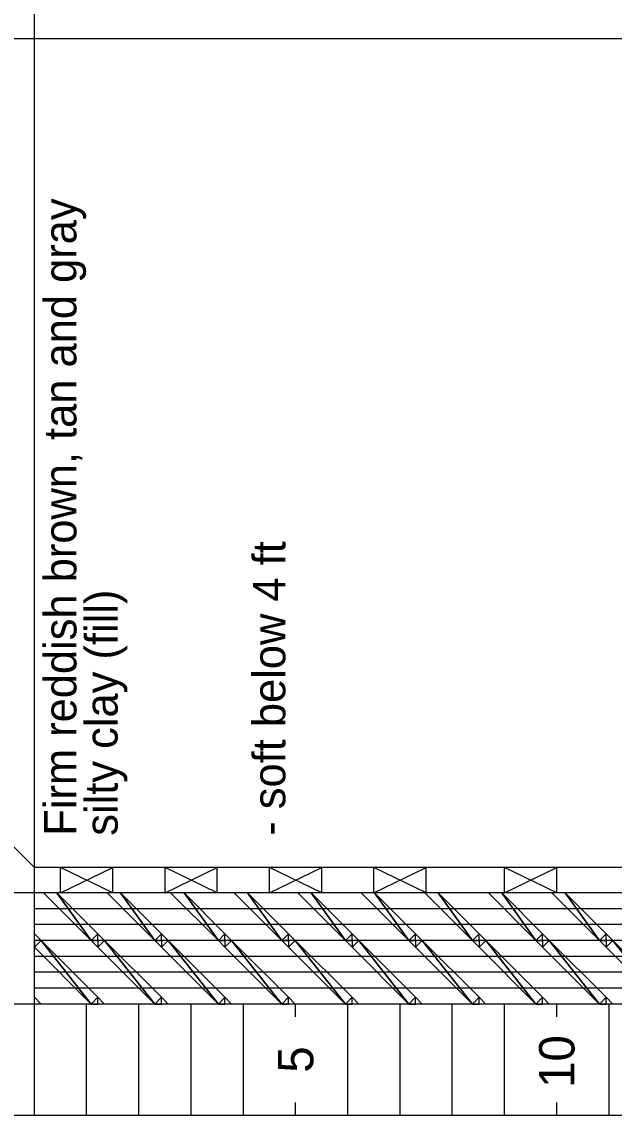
# Model space of a CAD drawing. Extents: x 1313964 to 1316843, y 2087046 to 2096619.
# Drawn here: x 1313989.13 to 1314000.47, y 2089818.7 to 2089839.64 of the extents above; entities that cross this region are included whole.
import ezdxf

# ---------------------------------------------------------------- set-up
doc = ezdxf.new("R2010")
doc.units = 0
doc.layers.add('B-Sub-Contour', color=7, linetype='Continuous')

msp = doc.modelspace()

# ---------------------------------------------------------------- linework, layer by layer
at = {"layer": 'B-Sub-Contour'}
for points in [[(1314036.804, 2089818.705), (1314036.804, 2089861.576), (1313975.385, 2089861.576), (1313975.385, 2089818.705), (1314036.804, 2089818.705)], [(1313989.372, 2089818.705), (1313989.372, 2089861.576)], [(1314034.372, 2089839.319), (1313982.683, 2089839.319)], [(1313989.372, 2089823.448), (1313988.824, 2089823.995)], [(1314034.372, 2089823.448), (1313989.372, 2089823.448)], [(1313989.872, 2089822.961), (1313990.872, 2089823.448)], [(1313990.872, 2089822.961), (1313989.872, 2089823.448)], [(1313989.872, 2089822.961), (1313989.872, 2089823.448)], [(1313990.872, 2089822.961), (1313990.872, 2089823.448)], [(1313991.872, 2089822.961), (1313992.872, 2089823.448)], [(1313992.872, 2089822.961), (1313991.872, 2089823.448)], [(1313991.872, 2089822.961), (1313991.872, 2089823.448)], [(1313992.872, 2089822.961), (1313992.872, 2089823.448)], [(1313993.872, 2089822.961), (1313994.872, 2089823.448)], [(1313994.872, 2089822.961), (1313993.872, 2089823.448)], [(1313993.872, 2089822.961), (1313993.872, 2089823.448)], [(1313994.872, 2089822.961), (1313994.872, 2089823.448)], [(1313995.872, 2089822.961), (1313996.872, 2089823.448)], [(1313996.872, 2089822.961), (1313995.872, 2089823.448)], [(1313995.872, 2089822.961), (1313995.872, 2089823.448)], [(1313996.872, 2089822.961), (1313996.872, 2089823.448)], [(1313998.372, 2089822.961), (1313999.372, 2089823.448)], [(1313999.372, 2089822.961), (1313998.372, 2089823.448)], [(1313998.372, 2089822.961), (1313998.372, 2089823.448)], [(1313999.372, 2089822.961), (1313999.372, 2089823.448)], [(1314034.372, 2089822.961), (1313982.683, 2089822.961)], [(1314002.372, 2089822.657), (1313989.372, 2089822.657)], [(1314002.372, 2089822.353), (1313989.372, 2089822.353)], [(1314002.372, 2089822.049), (1313989.372, 2089822.049)], [(1314002.372, 2089821.745), (1313989.372, 2089821.745)], [(1314002.372, 2089821.441), (1313989.372, 2089821.441)], [(1314002.372, 2089821.137), (1313989.372, 2089821.137)], [(1314034.372, 2089820.833), (1313982.683, 2089820.833)], [(1313989.372, 2089820.59), (1313989.372, 2089820.833)], [(1313989.372, 2089820.59), (1313989.372, 2089820.833)], [(1313990.372, 2089818.705), (1313990.372, 2089820.833)], [(1313991.372, 2089818.705), (1313991.372, 2089820.833)], [(1313991.372, 2089818.705), (1313991.372, 2089820.833)], [(1313992.372, 2089818.705), (1313992.372, 2089820.833)], [(1313993.372, 2089818.705), (1313993.372, 2089820.833)], [(1313993.372, 2089818.705), (1313993.372, 2089820.833)], [(1313994.372, 2089820.59), (1313994.372, 2089820.833)], [(1313995.372, 2089818.705), (1313995.372, 2089820.833)], [(1313995.372, 2089818.705), (1313995.372, 2089820.833)], [(1313996.372, 2089818.705), (1313996.372, 2089820.833)], [(1313997.372, 2089818.705), (1313997.372, 2089820.833)], [(1313997.372, 2089818.705), (1313997.372, 2089820.833)], [(1313998.372, 2089818.705), (1313998.372, 2089820.833)], [(1313999.372, 2089820.59), (1313999.372, 2089820.833)], [(1313999.372, 2089820.59), (1313999.372, 2089820.833)], [(1314000.372, 2089818.705), (1314000.372, 2089820.833)], [(1313989.372, 2089818.705), (1313989.372, 2089818.948)], [(1313989.372, 2089818.705), (1313989.372, 2089818.948)], [(1313994.372, 2089818.705), (1313994.372, 2089818.948)], [(1313999.372, 2089818.705), (1313999.372, 2089818.948)], [(1313999.372, 2089818.705), (1313999.372, 2089818.948)]]:
    msp.add_lwpolyline(points, dxfattribs=at)
for points in [[(1313990.46, 2089822.049), (1313989.803, 2089822.961), (1313989.548, 2089822.961), (1313990.46, 2089822.049)], [(1313990.46, 2089822.049), (1313990.588, 2089822.177), (1313989.803, 2089822.961), (1313990.46, 2089822.049)], [(1313991.676, 2089822.049), (1313991.02, 2089822.961), (1313990.764, 2089822.961), (1313991.676, 2089822.049)], [(1313991.676, 2089822.049), (1313991.804, 2089822.177), (1313991.02, 2089822.961), (1313991.676, 2089822.049)], [(1313992.893, 2089822.049), (1313992.236, 2089822.961), (1313991.98, 2089822.961), (1313992.893, 2089822.049)], [(1313992.893, 2089822.049), (1313993.02, 2089822.177), (1313992.236, 2089822.961), (1313992.893, 2089822.049)], [(1313994.109, 2089822.049), (1313993.452, 2089822.961), (1313993.197, 2089822.961), (1313994.109, 2089822.049)], [(1313994.109, 2089822.049), (1313994.237, 2089822.177), (1313993.452, 2089822.961), (1313994.109, 2089822.049)], [(1313995.325, 2089822.049), (1313994.668, 2089822.961), (1313994.413, 2089822.961), (1313995.325, 2089822.049)], [(1313995.325, 2089822.049), (1313995.453, 2089822.177), (1313994.668, 2089822.961), (1313995.325, 2089822.049)], [(1313996.541, 2089822.049), (1313995.885, 2089822.961), (1313995.629, 2089822.961), (1313996.541, 2089822.049)], [(1313996.541, 2089822.049), (1313996.669, 2089822.177), (1313995.885, 2089822.961), (1313996.541, 2089822.049)], [(1313997.757, 2089822.049), (1313997.101, 2089822.961), (1313996.845, 2089822.961), (1313997.757, 2089822.049)], [(1313997.757, 2089822.049), (1313997.885, 2089822.177), (1313997.101, 2089822.961), (1313997.757, 2089822.049)], [(1313998.974, 2089822.049), (1313998.317, 2089822.961), (1313998.062, 2089822.961), (1313998.974, 2089822.049)], [(1313998.974, 2089822.049), (1313999.101, 2089822.177), (1313998.317, 2089822.961), (1313998.974, 2089822.049)], [(1314000.19, 2089822.049), (1313999.533, 2089822.961), (1313999.278, 2089822.961), (1314000.19, 2089822.049)], [(1314000.19, 2089822.049), (1314000.318, 2089822.177), (1313999.533, 2089822.961), (1314000.19, 2089822.049)], [(1313989.499, 2089822.049), (1313989.372, 2089822.049), (1313989.372, 2089822.177), (1313989.499, 2089822.049)], [(1313989.499, 2089822.049), (1313989.372, 2089822.049), (1313989.372, 2089821.922), (1313989.499, 2089822.049)], [(1313990.46, 2089820.833), (1313989.499, 2089822.049), (1313989.372, 2089821.922), (1313990.46, 2089820.833)], [(1313990.46, 2089820.833), (1313990.588, 2089820.961), (1313989.499, 2089822.049), (1313990.46, 2089820.833)], [(1313990.46, 2089822.049), (1313990.588, 2089822.049), (1313990.588, 2089822.177), (1313990.46, 2089822.049)], [(1313990.588, 2089822.049), (1313990.588, 2089821.922), (1313990.46, 2089822.049), (1313990.588, 2089822.049)], [(1313990.716, 2089822.049), (1313990.588, 2089822.049), (1313990.588, 2089822.177), (1313990.716, 2089822.049)], [(1313990.716, 2089822.049), (1313990.588, 2089822.049), (1313990.588, 2089821.922), (1313990.716, 2089822.049)], [(1313991.676, 2089820.833), (1313990.716, 2089822.049), (1313990.588, 2089821.922), (1313991.676, 2089820.833)], [(1313991.676, 2089820.833), (1313991.804, 2089820.961), (1313990.716, 2089822.049), (1313991.676, 2089820.833)], [(1313991.676, 2089822.049), (1313991.804, 2089822.049), (1313991.804, 2089822.177), (1313991.676, 2089822.049)], [(1313991.804, 2089822.049), (1313991.804, 2089821.922), (1313991.676, 2089822.049), (1313991.804, 2089822.049)], [(1313991.932, 2089822.049), (1313991.804, 2089822.049), (1313991.804, 2089822.177), (1313991.932, 2089822.049)], [(1313991.932, 2089822.049), (1313991.804, 2089822.049), (1313991.804, 2089821.922), (1313991.932, 2089822.049)], [(1313992.893, 2089820.833), (1313991.932, 2089822.049), (1313991.804, 2089821.922), (1313992.893, 2089820.833)], [(1313992.893, 2089820.833), (1313993.02, 2089820.961), (1313991.932, 2089822.049), (1313992.893, 2089820.833)], [(1313992.893, 2089822.049), (1313993.02, 2089822.049), (1313993.02, 2089822.177), (1313992.893, 2089822.049)], [(1313993.02, 2089822.049), (1313993.02, 2089821.922), (1313992.893, 2089822.049), (1313993.02, 2089822.049)], [(1313993.148, 2089822.049), (1313993.02, 2089822.049), (1313993.02, 2089822.177), (1313993.148, 2089822.049)], [(1313993.148, 2089822.049), (1313993.02, 2089822.049), (1313993.02, 2089821.922), (1313993.148, 2089822.049)], [(1313994.109, 2089820.833), (1313993.148, 2089822.049), (1313993.02, 2089821.922), (1313994.109, 2089820.833)], [(1313994.109, 2089820.833), (1313994.237, 2089820.961), (1313993.148, 2089822.049), (1313994.109, 2089820.833)], [(1313994.109, 2089822.049), (1313994.237, 2089822.049), (1313994.237, 2089822.177), (1313994.109, 2089822.049)], [(1313994.237, 2089822.049), (1313994.237, 2089821.922), (1313994.109, 2089822.049), (1313994.237, 2089822.049)], [(1313994.364, 2089822.049), (1313994.237, 2089822.049), (1313994.237, 2089822.177), (1313994.364, 2089822.049)], [(1313994.364, 2089822.049), (1313994.237, 2089822.049), (1313994.237, 2089821.922), (1313994.364, 2089822.049)], [(1313995.325, 2089820.833), (1313994.364, 2089822.049), (1313994.237, 2089821.922), (1313995.325, 2089820.833)], [(1313995.325, 2089820.833), (1313995.453, 2089820.961), (1313994.364, 2089822.049), (1313995.325, 2089820.833)], [(1313995.325, 2089822.049), (1313995.453, 2089822.049), (1313995.453, 2089822.177), (1313995.325, 2089822.049)], [(1313995.453, 2089822.049), (1313995.453, 2089821.922), (1313995.325, 2089822.049), (1313995.453, 2089822.049)], [(1313995.58, 2089822.049), (1313995.453, 2089822.049), (1313995.453, 2089822.177), (1313995.58, 2089822.049)], [(1313995.58, 2089822.049), (1313995.453, 2089822.049), (1313995.453, 2089821.922), (1313995.58, 2089822.049)], [(1313996.541, 2089820.833), (1313995.58, 2089822.049), (1313995.453, 2089821.922), (1313996.541, 2089820.833)], [(1313996.541, 2089820.833), (1313996.669, 2089820.961), (1313995.58, 2089822.049), (1313996.541, 2089820.833)], [(1313996.541, 2089822.049), (1313996.669, 2089822.049), (1313996.669, 2089822.177), (1313996.541, 2089822.049)], [(1313996.669, 2089822.049), (1313996.669, 2089821.922), (1313996.541, 2089822.049), (1313996.669, 2089822.049)], [(1313996.797, 2089822.049), (1313996.669, 2089822.049), (1313996.669, 2089822.177), (1313996.797, 2089822.049)], [(1313996.797, 2089822.049), (1313996.669, 2089822.049), (1313996.669, 2089821.922), (1313996.797, 2089822.049)], [(1313997.757, 2089820.833), (1313996.797, 2089822.049), (1313996.669, 2089821.922), (1313997.757, 2089820.833)], [(1313997.757, 2089820.833), (1313997.885, 2089820.961), (1313996.797, 2089822.049), (1313997.757, 2089820.833)], [(1313997.757, 2089822.049), (1313997.885, 2089822.049), (1313997.885, 2089822.177), (1313997.757, 2089822.049)], [(1313997.885, 2089822.049), (1313997.885, 2089821.922), (1313997.757, 2089822.049), (1313997.885, 2089822.049)], [(1313998.013, 2089822.049), (1313997.885, 2089822.049), (1313997.885, 2089822.177), (1313998.013, 2089822.049)], [(1313998.013, 2089822.049), (1313997.885, 2089822.049), (1313997.885, 2089821.922), (1313998.013, 2089822.049)], [(1313998.974, 2089820.833), (1313998.013, 2089822.049), (1313997.885, 2089821.922), (1313998.974, 2089820.833)], [(1313998.974, 2089820.833), (1313999.101, 2089820.961), (1313998.013, 2089822.049), (1313998.974, 2089820.833)], [(1313998.974, 2089822.049), (1313999.101, 2089822.049), (1313999.101, 2089822.177), (1313998.974, 2089822.049)], [(1313999.101, 2089822.049), (1313999.101, 2089821.922), (1313998.974, 2089822.049), (1313999.101, 2089822.049)], [(1313999.229, 2089822.049), (1313999.101, 2089822.049), (1313999.101, 2089822.177), (1313999.229, 2089822.049)], [(1313999.229, 2089822.049), (1313999.101, 2089822.049), (1313999.101, 2089821.922), (1313999.229, 2089822.049)], [(1314000.19, 2089820.833), (1313999.229, 2089822.049), (1313999.101, 2089821.922), (1314000.19, 2089820.833)], [(1314000.19, 2089820.833), (1314000.318, 2089820.961), (1313999.229, 2089822.049), (1314000.19, 2089820.833)], [(1314000.19, 2089822.049), (1314000.318, 2089822.049), (1314000.318, 2089822.177), (1314000.19, 2089822.049)], [(1314000.318, 2089822.049), (1314000.318, 2089821.922), (1314000.19, 2089822.049), (1314000.318, 2089822.049)], [(1314000.445, 2089822.049), (1314000.318, 2089822.049), (1314000.318, 2089822.177), (1314000.445, 2089822.049)], [(1314000.445, 2089822.049), (1314000.318, 2089822.049), (1314000.318, 2089821.922), (1314000.445, 2089822.049)], [(1314001.406, 2089820.833), (1314000.445, 2089822.049), (1314000.318, 2089821.922), (1314001.406, 2089820.833)], [(1314001.406, 2089820.833), (1314001.534, 2089820.961), (1314000.445, 2089822.049), (1314001.406, 2089820.833)], [(1313989.499, 2089820.833), (1313989.372, 2089820.833), (1313989.372, 2089820.961), (1313989.499, 2089820.833)], [(1313990.46, 2089820.833), (1313990.588, 2089820.833), (1313990.588, 2089820.961), (1313990.46, 2089820.833)], [(1313990.716, 2089820.833), (1313990.588, 2089820.833), (1313990.588, 2089820.961), (1313990.716, 2089820.833)], [(1313991.676, 2089820.833), (1313991.804, 2089820.833), (1313991.804, 2089820.961), (1313991.676, 2089820.833)], [(1313991.932, 2089820.833), (1313991.804, 2089820.833), (1313991.804, 2089820.961), (1313991.932, 2089820.833)], [(1313992.893, 2089820.833), (1313993.02, 2089820.833), (1313993.02, 2089820.961), (1313992.893, 2089820.833)], [(1313993.148, 2089820.833), (1313993.02, 2089820.833), (1313993.02, 2089820.961), (1313993.148, 2089820.833)], [(1313994.109, 2089820.833), (1313994.237, 2089820.833), (1313994.237, 2089820.961), (1313994.109, 2089820.833)], [(1313994.364, 2089820.833), (1313994.237, 2089820.833), (1313994.237, 2089820.961), (1313994.364, 2089820.833)], [(1313995.325, 2089820.833), (1313995.453, 2089820.833), (1313995.453, 2089820.961), (1313995.325, 2089820.833)], [(1313995.58, 2089820.833), (1313995.453, 2089820.833), (1313995.453, 2089820.961), (1313995.58, 2089820.833)], [(1313996.541, 2089820.833), (1313996.669, 2089820.833), (1313996.669, 2089820.961), (1313996.541, 2089820.833)], [(1313996.797, 2089820.833), (1313996.669, 2089820.833), (1313996.669, 2089820.961), (1313996.797, 2089820.833)], [(1313997.757, 2089820.833), (1313997.885, 2089820.833), (1313997.885, 2089820.961), (1313997.757, 2089820.833)], [(1313998.013, 2089820.833), (1313997.885, 2089820.833), (1313997.885, 2089820.961), (1313998.013, 2089820.833)], [(1313998.974, 2089820.833), (1313999.101, 2089820.833), (1313999.101, 2089820.961), (1313998.974, 2089820.833)], [(1313999.229, 2089820.833), (1313999.101, 2089820.833), (1313999.101, 2089820.961), (1313999.229, 2089820.833)], [(1314000.19, 2089820.833), (1314000.318, 2089820.833), (1314000.318, 2089820.961), (1314000.19, 2089820.833)], [(1314000.445, 2089820.833), (1314000.318, 2089820.833), (1314000.318, 2089820.961), (1314000.445, 2089820.833)]]:
    msp.add_lwpolyline(points, close=True, dxfattribs=at)

# ---------------------------------------------------------------- texts
for s, height, p in [('Firm reddish brown, tan and gray', 0.62209, (1313990.176, 2089824.056)), ('- soft below 4 ft', 0.62209, (1313994.176, 2089824.056)), ('silty clay (fill)', 0.62209, (1313990.966, 2089824.056)), ('10', 0.6786, (1313999.711, 2089819.227)), ('10', 0.6786, (1313999.711, 2089819.227)), ('5', 0.679, (1313994.711, 2089819.517))]:
    msp.add_text(s, height=height, rotation=90, dxfattribs=at).set_placement(p)

doc.saveas('drawing.dxf')
